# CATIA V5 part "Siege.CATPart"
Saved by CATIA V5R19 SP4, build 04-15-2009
Part number: Siege
Bounding box of the stored display mesh (mm): x 174 to 674, y 1030 to 1080, z 116.667 to 450
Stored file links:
  G:\EU_thinkMotion\CFAO_2010\MMS_groupe1\MMS_groupe1\OK\rragonneau\rragonneau\Siege.CATPart
  F:\Squelette\Deambulateur.CATProduct
  G:\EU_thinkMotion\CFAO_2010\MMS_groupe1\MMS_groupe1\OK\rragonneau\rragonneau\Montants.CATPart
  G:\EU_thinkMotion\CFAO_2010\MMS_groupe1\MMS_groupe1\OK\rragonneau\rragonneau\squelette siege.CATPart
  G:\EU_thinkMotion\CFAO_2010\MMS_groupe1\MMS_groupe1\OK\rragonneau\rragonneau\squelette de base.CATPart
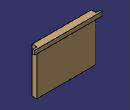
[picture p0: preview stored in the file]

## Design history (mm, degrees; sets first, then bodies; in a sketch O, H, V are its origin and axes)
External parameters (linked from other documents)
  External.largeur_siege = 500 mm
  `External.diam_moyeu_ext / epaisseur_bras&montant` = 60 mm
Set1
  Sketch1 on Plane1, origin (0, 1050, -650), H (1, 0, 0), V (0, 0, 1)
    line L1 (644, 1100) -> (204, 1100)
    line L2 (204, 1100) -> (204, 766.6667)
    line L3 (204, 766.6667) -> (644, 766.6667)
    line L4 (644, 766.6667) -> (644, 1100)
    reference projected line E1 (-576, 1050) -> (424, 1050) from Line1
    reference intersected line E2 through (204, 0) direction (0, 1) from DatumSurface1
    length L1 = 440 {= External.largeur_siege -`External.diam_moyeu_ext / epaisseur_bras&montant`}
    distance E1 L1 = 50
    length L4 = 333.3333 {= External.largeur_siege *2/3}
    horizontal: L1 H, L3 H
    vertical: L2 V, L4 V
    coincidence: L2 E2
Set2
  Plane1: linked copy from another document
  DatumSurface1: linked copy from another document
  Line1: linked copy from another document
  Point1 to Point3: linked copy from another document
Body1 (main body)
  Pad1: profile Sketch1, direction (0, -1, 0), length 20, opposite side length 15 {= `External.diam_moyeu_ext / epaisseur_bras&montant` /4}
  Sketch2 on face of Pad1 from Sketch1.L4, origin (644, 1818.7239, 399.234), H (0, 1, 0), V (0, 0, 1)
    point P1 (-768.7239, 0.766)
    reference projected point E1 (-768.7239, 0.766) from Point1
    coincidence: P1 E1
  Hole1: placed by Sketch2, at (644, 1050, 400) direction (-1, 0, 0), diameter 15 {= `External.diam_moyeu_ext / epaisseur_bras&montant` /4}, through (limit type 3)
  Sketch3 on start face of Pad1, origin (0, 1065, -675.1134), H (1, 0, 0), V (0, 0, -1)
    line L1 (674, -1095.1134) -> (174, -1095.1134)
    line L2 (174, -1095.1134) -> (174, -1125.1134)
    line L3 (174, -1125.1134) -> (674, -1125.1134)
    line L4 (674, -1125.1134) -> (674, -1095.1134)
    reference projected point E1 (674, -1225.1134) from Point2
    reference projected point E2 (174, -1225.1134) from Point3
    reference projected line E3 (394, -1125.1134) -> (-546, -1125.1134) from edge [start face of Pad1 | face of Pad1 from Sketch1.L1]
    length L4 = 30
    horizontal: L1 H, L3 H
    vertical: L2 V, L4 V
    coincidence: L4 E1, L2 E2, L3 E3
  Pad2: profile Sketch3, direction (0, 1, 0), length 15 {= `External.diam_moyeu_ext / epaisseur_bras&montant` /4}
